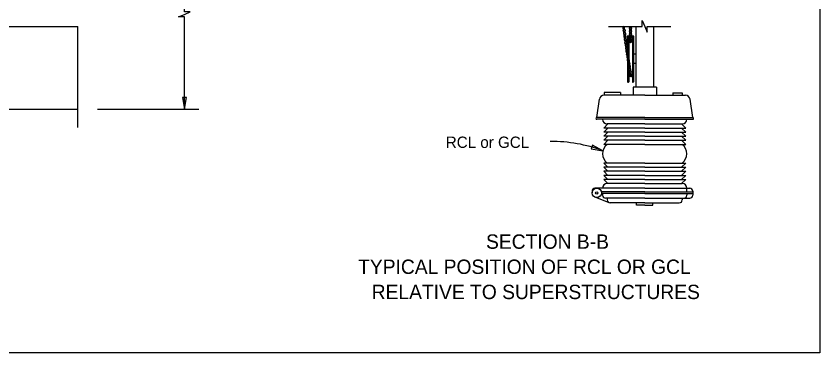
# Model space of a CAD drawing. Extents: x 83976.6 to 84012, y 72958.9 to 72975.6.
# Drawn here: x 83989.96 to 83997.11, y 72960.16 to 72963.16 of the extents above; entities that cross this region are included whole.
import ezdxf

# ---------------------------------------------------------------- set-up
doc = ezdxf.new("R2010")
doc.units = 0
for name, color, linetype in [('DSText', 7, 'Continuous'), ('DSTitle', 7, 'Continuous'), ('Patterning', 7, 'Continuous'), ('RefPtStaTie', 7, 'Continuous'), ('SheetLines_dp', 7, 'Continuous'), ('SupstrConc', 7, 'Continuous')]:
    doc.layers.add(name, color=color, linetype=linetype)

msp = doc.modelspace()

# ---------------------------------------------------------------- linework, layer by layer
at = {"layer": 'DSText'}
for p, q in [((83995.4736, 72963.068), (83995.4736, 72962.5269)), ((83995.6319, 72963.068), (83995.6319, 72962.5269)), ((83995.6569, 72962.5269), (83995.4485, 72962.5269)), ((83995.4485, 72962.5268), (83995.4485, 72962.454)), ((83995.6569, 72962.5268), (83995.6569, 72962.454)), ((83995.1254, 72962.2562), (83995.1495, 72962.4185)), ((83995.1907, 72962.48), (83995.1907, 72962.454)), ((83995.3365, 72962.48), (83995.1907, 72962.48)), ((83995.5527, 72962.454), (83995.1907, 72962.454)), ((83995.3365, 72962.48), (83995.3365, 72962.454)), ((83995.5527, 72962.454), (83995.9146, 72962.454)), ((83995.8027, 72962.4748), (83995.886, 72962.4748)), ((83995.8027, 72962.4748), (83995.8027, 72962.454)), ((83995.886, 72962.4748), (83995.886, 72962.454)), ((83995.9797, 72962.2562), (83995.9557, 72962.4185)), ((83995.5526, 72962.2561), (83995.1254, 72962.2561)), ((83995.5526, 72962.2405), (83995.1254, 72962.2405)), ((83995.5526, 72962.2561), (83995.9798, 72962.2561)), ((83995.5526, 72962.2405), (83995.9798, 72962.2405)), ((83995.5526, 72962.1988), (83995.2193, 72962.1988)), ((83995.5527, 72962.1988), (83995.886, 72962.1988)), ((83995.5526, 72961.6675), (83995.2193, 72961.6675)), ((83995.5527, 72961.6675), (83995.886, 72961.6675)), ((83995.0839, 72961.5998), (83995.0839, 72961.5842)), ((83995.5527, 72961.6258), (83995.1099, 72961.6258)), ((83995.5527, 72961.5945), (83995.1659, 72961.5945)), ((83995.5527, 72961.5789), (83995.1669, 72961.5789)), ((83995.1777, 72961.579), (83995.1777, 72961.5633)), ((83995.5527, 72961.6258), (83995.9538, 72961.6258)), ((83995.5527, 72961.5945), (83995.9798, 72961.5945)), ((83995.5527, 72961.5789), (83995.9798, 72961.5789)), ((83995.9277, 72961.5946), (83995.9277, 72961.6258)), ((83995.9277, 72961.579), (83995.9277, 72961.5633)), ((83995.9798, 72961.5998), (83995.9798, 72961.5633)), ((83995.2361, 72961.4973), (83995.1107, 72961.5453)), ((83995.5527, 72961.5373), (83995.2037, 72961.5373)), ((83995.2194, 72961.5373), (83995.2194, 72961.5216)), ((83995.5527, 72961.4956), (83995.2454, 72961.4956)), ((83995.4798, 72961.4747), (83995.4798, 72961.4955)), ((83995.5527, 72961.5373), (83995.9538, 72961.5373)), ((83995.5527, 72961.4956), (83995.86, 72961.4956)), ((83995.6256, 72961.4747), (83995.6256, 72961.4955)), ((83995.886, 72961.5373), (83995.886, 72961.5216)), ((83995.5527, 72961.4747), (83995.4798, 72961.4747)), ((83995.5527, 72961.4747), (83995.6256, 72961.4747))]:
    msp.add_line(p, q, dxfattribs=at)
for radius in [0.0416, 0.0104]:
    msp.add_circle((83995.1255, 72961.5842), radius, dxfattribs=at)
for centre, radius, start, end in [((83995.1907, 72962.4124), 0.0417, 90, 171.57567), ((83995.9145, 72962.4124), 0.0417, 8.42433, 90), ((83995.1254, 72962.2483), 0.00781, 90, 270), ((83995.2193, 72962.2405), 0.0417, 180, 270), ((83995.886, 72962.2405), 0.0417, 270, 0), ((83995.9798, 72962.2483), 0.00781, 270, 90), ((83995.2193, 72961.6258), 0.0417, 90, 180), ((83995.886, 72961.6258), 0.0417, 0, 90), ((83995.1099, 72961.5998), 0.026, 90, 180), ((83995.2037, 72961.5633), 0.026, 180, 270), ((83995.9017, 72961.5633), 0.026, 270, 0), ((83995.9538, 72961.5998), 0.026, 0, 90), ((83995.9538, 72961.5633), 0.026, 270.00345, 0), ((83995.2454, 72961.5216), 0.026, 180, 270), ((83995.86, 72961.5216), 0.026, 270, 0)]:
    msp.add_arc(centre, radius, start, end, dxfattribs=at)
at = {"layer": 'DSTitle'}
for p, q in [((83995.4008, 72962.9813), (83995.4008, 72962.5748)), ((83995.4112, 72962.9813), (83995.4112, 72962.5748)), ((83995.4268, 72962.9865), (83995.4268, 72962.9241)), ((83995.4424, 72962.9813), (83995.4424, 72962.5748)), ((83995.4528, 72962.9813), (83995.4528, 72962.5748)), ((83995.4736, 72962.8198), (83995.4528, 72962.8198)), ((83995.4736, 72962.7364), (83995.4528, 72962.7364)), ((83995.2245, 72962.1988), (83995.188, 72962.1623)), ((83995.2245, 72962.1623), (83995.188, 72962.1259)), ((83995.5528, 72962.1622), (83995.1881, 72962.1622)), ((83995.5527, 72962.1622), (83995.9173, 72962.1622)), ((83995.8808, 72962.1988), (83995.9173, 72962.1623)), ((83995.8808, 72962.1623), (83995.9173, 72962.1259)), ((83995.2245, 72962.1259), (83995.188, 72962.0894)), ((83995.2245, 72962.0894), (83995.188, 72962.053)), ((83995.5528, 72962.1258), (83995.1881, 72962.1258)), ((83995.5528, 72962.0893), (83995.1881, 72962.0893)), ((83995.5527, 72962.1258), (83995.9173, 72962.1258)), ((83995.5527, 72962.0893), (83995.9173, 72962.0893)), ((83995.8808, 72962.1259), (83995.9173, 72962.0894)), ((83995.8808, 72962.0894), (83995.9173, 72962.053)), ((83995.2245, 72962.053), (83995.188, 72962.0165)), ((83995.5528, 72962.0529), (83995.1881, 72962.0529)), ((83995.5528, 72962.0164), (83995.1881, 72962.0164)), ((83995.5527, 72962.0529), (83995.9173, 72962.0529)), ((83995.5527, 72962.0164), (83995.9173, 72962.0164)), ((83995.8808, 72962.053), (83995.9173, 72962.0165)), ((83995.2245, 72961.8134), (83995.188, 72961.8498)), ((83995.5528, 72961.8497), (83995.1881, 72961.8497)), ((83995.5527, 72961.8497), (83995.9173, 72961.8497)), ((83995.8808, 72961.8134), (83995.9173, 72961.8498)), ((83995.2245, 72961.7769), (83995.188, 72961.8134)), ((83995.2245, 72961.7405), (83995.188, 72961.7769)), ((83995.5528, 72961.8133), (83995.1881, 72961.8133)), ((83995.5528, 72961.7768), (83995.1881, 72961.7768)), ((83995.5527, 72961.8133), (83995.9173, 72961.8133)), ((83995.5527, 72961.7768), (83995.9173, 72961.7768)), ((83995.8808, 72961.7769), (83995.9173, 72961.8134)), ((83995.8808, 72961.7405), (83995.9173, 72961.7769)), ((83995.2245, 72961.704), (83995.188, 72961.7405)), ((83995.2245, 72961.6675), (83995.188, 72961.704)), ((83995.5528, 72961.7404), (83995.1881, 72961.7404)), ((83995.5528, 72961.7039), (83995.1881, 72961.7039)), ((83995.5527, 72961.7404), (83995.9173, 72961.7404)), ((83995.5527, 72961.7039), (83995.9173, 72961.7039)), ((83995.8808, 72961.704), (83995.9173, 72961.7405)), ((83995.8808, 72961.6675), (83995.9173, 72961.704))]:
    msp.add_line(p, q, dxfattribs=at)
for centre, radius, start, end in [((83995.406, 72962.9813), 0.0052, 0.00303, 179.61227), ((83995.4268, 72962.9397), 0.0156, 180, 359.8848), ((83995.4476, 72962.9813), 0.0052, 0.38773, 180.00117), ((83995.406, 72962.5748), 0.0052, 180.38773, 359.99697), ((83995.4268, 72962.6164), 0.0156, 0.1152, 180), ((83995.4476, 72962.5748), 0.0052, 179.99883, 359.61227), ((83995.2817, 72961.9332), 0.1041, 126.81262, 233.18738), ((83995.8236, 72961.9332), 0.1041, 306.81262, 53.18738)]:
    msp.add_arc(centre, radius, start, end, dxfattribs=at)
for centre, major_axis, ratio, start_param, end_param in [((83995.3658, 72963.055), (-0.0022, 0.0152), 0.530594, 0.467517, 5.663262), ((83995.3658, 72963.055), (-0.0019, 0.0131), 0.458548, 0.090049, 6.06136), ((83995.362, 72963.0813), (-0.0022, 0.0152), 0.530594, 2.556023, 3.574757), ((83995.4258, 72963.0784), (-0.0001, 0.0153), 0.530594, 2.31426, 3.960984), ((83995.4258, 72963.0784), (-0.0001, 0.0133), 0.458548, 2.4686, 3.807723), ((83995.427, 72962.919), (-0.0001, 0.0153), 0.530594, 5.178718, 7.393601), ((83995.427, 72962.919), (-0.0001, 0.0133), 0.458548, 5.185958, 7.38546)]:
    msp.add_ellipse(centre, major_axis=major_axis, ratio=ratio, start_param=start_param, end_param=end_param, dxfattribs=at)
for centre, major_axis, ratio in [((83995.426, 72963.0519), (-0.0001, 0.0153), 0.530594), ((83995.426, 72963.0519), (-0.0001, 0.0133), 0.458548), ((83995.3696, 72963.0287), (-0.0022, 0.0152), 0.530594), ((83995.3696, 72963.0287), (-0.0019, 0.0131), 0.458548), ((83995.3734, 72963.0024), (-0.0022, 0.0152), 0.530594), ((83995.3734, 72963.0024), (-0.0019, 0.0131), 0.458548), ((83995.3772, 72962.9761), (-0.0022, 0.0152), 0.530594), ((83995.4262, 72963.0253), (-0.0001, 0.0153), 0.530594), ((83995.4264, 72962.9987), (-0.0001, 0.0153), 0.530594), ((83995.4262, 72963.0253), (-0.0001, 0.0133), 0.458548), ((83995.4264, 72962.9987), (-0.0001, 0.0133), 0.458548), ((83995.3772, 72962.9761), (-0.0019, 0.0131), 0.458548), ((83995.3809, 72962.9498), (-0.0022, 0.0152), 0.530594), ((83995.3809, 72962.9498), (-0.0019, 0.0131), 0.458548), ((83995.3847, 72962.9235), (-0.0022, 0.0152), 0.530594), ((83995.3847, 72962.9235), (-0.0019, 0.0131), 0.458548), ((83995.4266, 72962.9722), (-0.0001, 0.0153), 0.530594), ((83995.4268, 72962.9456), (-0.0001, 0.0153), 0.530594), ((83995.4266, 72962.9722), (-0.0001, 0.0133), 0.458548), ((83995.4268, 72962.9456), (-0.0001, 0.0133), 0.458548), ((83995.3885, 72962.8972), (-0.0022, 0.0152), 0.530594), ((83995.3885, 72962.8972), (-0.0019, 0.0131), 0.458548), ((83995.3923, 72962.8709), (-0.0022, 0.0152), 0.530594), ((83995.3923, 72962.8709), (-0.0019, 0.0131), 0.458548), ((83995.3961, 72962.8446), (-0.0022, 0.0152), 0.530594), ((83995.3961, 72962.8446), (-0.0019, 0.0131), 0.458548), ((83995.3999, 72962.8183), (-0.0022, 0.0152), 0.530594), ((83995.3999, 72962.8183), (-0.0019, 0.0131), 0.458548), ((83995.4036, 72962.792), (-0.0022, 0.0152), 0.530594), ((83995.4036, 72962.792), (-0.0019, 0.0131), 0.458548), ((83995.4074, 72962.7658), (-0.0022, 0.0152), 0.530594), ((83995.4074, 72962.7658), (-0.0019, 0.0131), 0.458548), ((83995.4112, 72962.7395), (-0.0022, 0.0152), 0.530594), ((83995.4112, 72962.7395), (-0.0019, 0.0131), 0.458548), ((83995.415, 72962.7132), (-0.0022, 0.0152), 0.530594), ((83995.415, 72962.7132), (-0.0019, 0.0131), 0.458548), ((83995.4188, 72962.6869), (-0.0022, 0.0152), 0.530594), ((83995.4188, 72962.6869), (-0.0019, 0.0131), 0.458548), ((83995.4226, 72962.6606), (-0.0022, 0.0152), 0.530594), ((83995.4226, 72962.6606), (-0.0019, 0.0131), 0.458548), ((83995.4263, 72962.6343), (-0.0022, 0.0152), 0.530594), ((83995.4263, 72962.6343), (-0.0019, 0.0131), 0.458548)]:
    msp.add_ellipse(centre, major_axis=major_axis, ratio=ratio, dxfattribs=at)
at = {"layer": 'RefPtStaTie'}
msp.add_lwpolyline([(83976.5859, 72973.1323), (83997.1112, 72973.1323), (83997.1112, 72960.1592), (83976.5859, 72960.1592)], close=True, dxfattribs=at)
at = {"layer": 'SheetLines_dp'}
msp.add_line((83990.6852, 72962.3289), (83991.5851, 72962.3289), dxfattribs=at)
for points in [[(83991.4578, 72962.3289), (83991.4578, 72963.1518), (83991.4061, 72963.1518), (83991.4578, 72963.1743), (83991.5094, 72963.1968), (83991.4578, 72963.1968), (83991.4578, 72964.9257)], [(83982.4439, 72963.068), (83986.7743, 72963.068), (83986.7743, 72963.1196), (83986.7968, 72963.068), (83986.8193, 72963.0163), (83986.8193, 72963.068), (83990.5105, 72963.068)], [(83990.5104, 72962.1667), (83990.5104, 72963.068)], [(83995.231, 72963.068), (83995.5303, 72963.068), (83995.5303, 72963.1197), (83995.5528, 72963.068), (83995.5753, 72963.0164), (83995.5753, 72963.068), (83995.7863, 72963.068)]]:
    msp.add_lwpolyline(points, dxfattribs=at)
for points in [[(83991.4578, 72962.3289), (83991.4754, 72962.433), (83991.4401, 72962.433)], [(83995.1812, 72961.9602), (83995.0882, 72962.0103), (83995.0769, 72961.9769)]]:
    msp.add_lwpolyline(points, close=True, dxfattribs=at)
msp.add_arc((83994.7284, 72960.7529), 1.2893, 69.44292, 90.68885, dxfattribs=at)
at = {"layer": 'SupstrConc'}
msp.add_line((83985.1651, 72962.3289), (83990.5104, 72962.3289), dxfattribs=at)

# ---------------------------------------------------------------- texts
at = {"layer": 'Patterning'}
msp.add_text('RCL or GCL', height=0.1008, dxfattribs=at).set_placement((83993.783, 72961.9853))
at = {"layer": 'SheetLines_dp'}
for s, p in [('SECTION B-B', (83994.1408, 72961.0868)), ('TYPICAL POSITION OF RCL OR GCL', (83993.0031, 72960.8628)), ('RELATIVE TO SUPERSTRUCTURES', (83993.1237, 72960.6387))]:
    msp.add_text(s, height=0.128, dxfattribs=at).set_placement(p)

doc.saveas('drawing.dxf')
